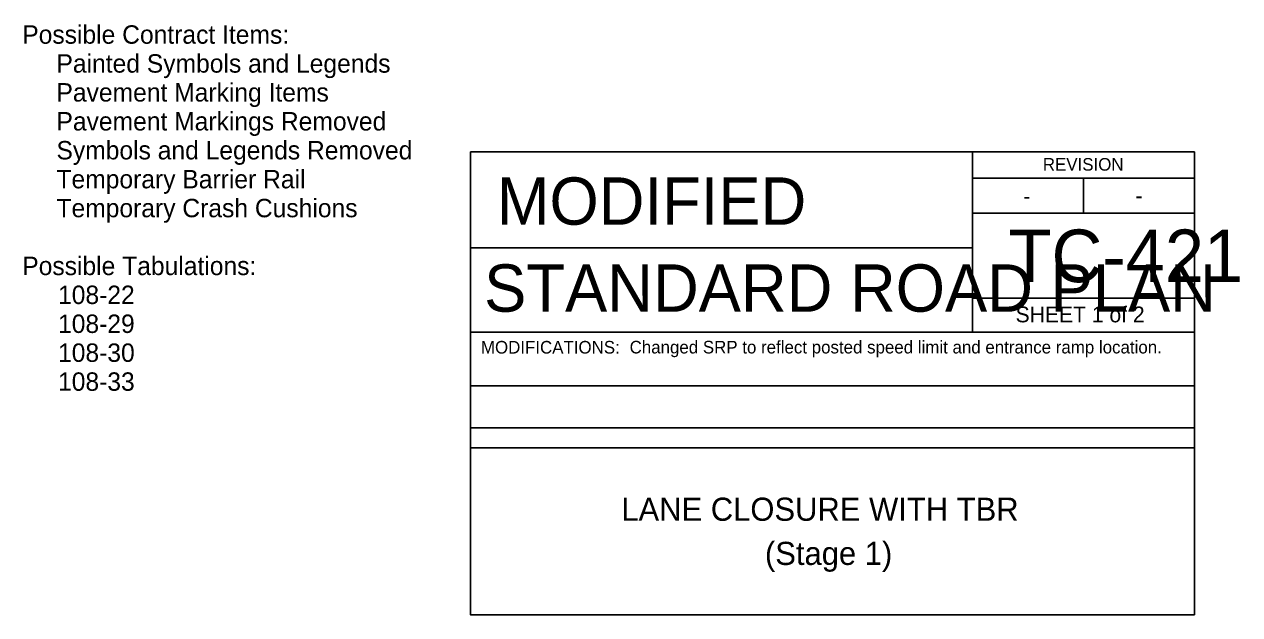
# Model space of a CAD drawing. Extents: x 10124 to 16850, y 7924 to 12166.
# Drawn here: x 12145 to 13300, y 7934 to 8495 of the extents above; entities that cross this region are included whole.
import ezdxf

# ---------------------------------------------------------------- set-up
doc = ezdxf.new("R2010")
doc.units = 0
for name, color, linetype in [('dsnStdBlock', 7, 'Continuous'), ('dsnStdBlockModified', 7, 'Continuous'), ('SheetText', 7, 'Continuous')]:
    doc.layers.add(name, color=color, linetype=linetype)

msp = doc.modelspace()

# ---------------------------------------------------------------- linework, layer by layer
at = {"layer": 'dsnStdBlock'}
for p, q in [((13045.9, 8374), (13045.9, 8282.7)), ((13045.9, 8349.1), (13256.8, 8349.1)), ((13151.3, 8349.1), (13151.3, 8315.9)), ((13045.9, 8315.9), (13256.8, 8315.9)), ((12568.8, 8282.7), (13045.9, 8282.7)), ((13045.9, 8282.7), (13045.9, 8202.7)), ((13256.8, 8234.9), (13045.9, 8234.9)), ((12568.8, 8202.7), (13256.8, 8202.7)), ((12568.8, 8151.7), (13256.8, 8151.7)), ((12568.8, 8111.7), (13256.8, 8111.7)), ((12568.8, 8092.7), (13256.8, 8092.7))]:
    msp.add_line(p, q, dxfattribs=at)
msp.add_lwpolyline([(12568.8, 8374), (13256.8, 8374), (13256.8, 7934), (12568.8, 7934)], close=True, dxfattribs=at)

# ---------------------------------------------------------------- texts
for s, height, p in [('REVISION', 12, (13112.8, 8356.2)), ('-', 15, (13094.3, 8324.6)), ('-', 15, (13200.9, 8325.1)), ('TC-421', 50, (13080.2, 8250.2)), ('STANDARD ROAD PLAN', 45.001, (12581.8, 8222.1)), ('SHEET 1 of 2', 15, (13086.9, 8212)), ('Changed SRP to reflect posted speed limit and entrance ramp location.', 12, (12720.1, 8182.4)), ('LANE CLOSURE WITH TBR', 22, (12712.2, 8023.3)), ('(Stage 1)', 22, (12848.7, 7981.3))]:
    msp.add_text(s, height=height, dxfattribs=at).set_placement(p)
at = {"layer": 'dsnStdBlockModified'}
for s, height, p in [('MODIFIED', 45, (12593.8, 8304.8)), ('MODIFICATIONS:', 12, (12578.8, 8182.3))]:
    msp.add_text(s, height=height, dxfattribs=at).set_placement(p)
at = {"layer": 'SheetText'}
for s, p in [('Possible Contract Items:', (12142.9, 8476.9)), ('     Painted Symbols and Legends', (12142.9, 8449.4)), ('     Pavement Marking Items', (12142.9, 8421.9)), ('     Pavement Markings Removed', (12142.9, 8394.4)), ('     Symbols and Legends Removed', (12142.9, 8366.9)), ('     Temporary Barrier Rail', (12142.9, 8339.4)), ('     Temporary Crash Cushions', (12142.9, 8311.9)), ('Possible Tabulations:', (12142.9, 8256.9)), ('108-22', (12176.9, 8229.4)), ('108-29', (12176.9, 8201.9)), ('108-30', (12176.9, 8174.4)), ('108-33', (12176.9, 8146.9))]:
    msp.add_text(s, height=17.5, dxfattribs=at).set_placement(p)

doc.saveas('drawing.dxf')
